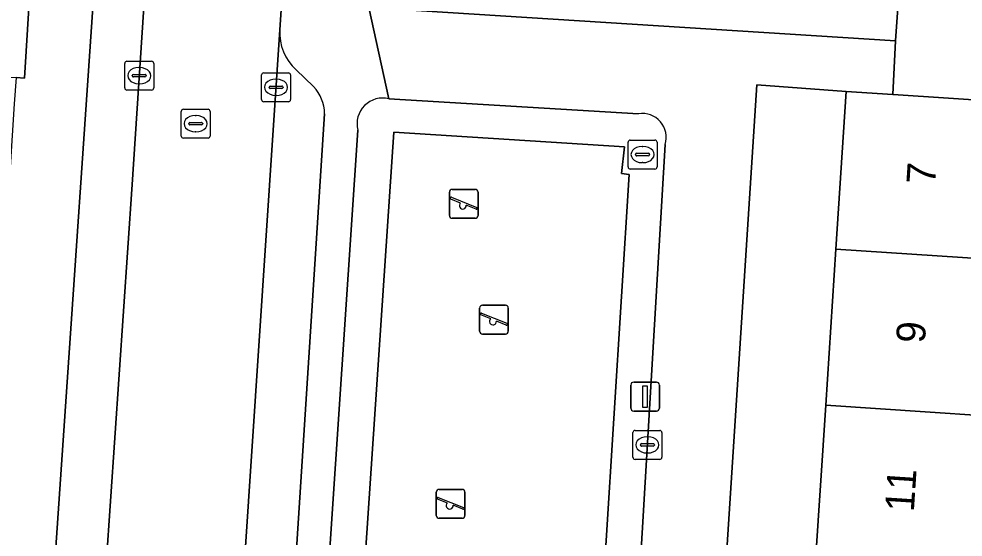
# Model space of a CAD drawing. Extents: x 160349 to 161355, y 381727 to 382854.
# Drawn here: x 160524.54 to 160557.19, y 382098.86 to 382116.79 of the extents above; entities that cross this region are included whole.
import ezdxf

# ---------------------------------------------------------------- set-up
doc = ezdxf.new("R2010")
doc.units = 0
for name, color, linetype in [('IMGEO_Erf', 7, 'Continuous'), ('IMGEO_Kolk', 7, 'Continuous'), ('IMGEO_Lichtmast', 7, 'Continuous'), ('IMGEO_Pand', 7, 'Continuous'), ('IMGEO_Pand_nummerreeks', 7, 'Continuous'), ('IMGEO_Parkeervlak_open', 7, 'Continuous'), ('IMGEO_Rijbaan_lokaal_open', 7, 'Continuous'), ('IMGEO_Rioolput', 7, 'Continuous'), ('IMGEO_Speelvoorziening', 7, 'Continuous'), ('IMGEO_Terreindeel_zand', 7, 'Continuous'), ('IMGEO_Voetpad_open', 7, 'Continuous')]:
    doc.layers.add(name, color=color, linetype=linetype)

msp = doc.modelspace()

# ---------------------------------------------------------------- linework, layer by layer
at = {"layer": 'IMGEO_Erf'}
msp.add_lwpolyline([(160554.283, 382136.365), (160554.009, 382131.874), (160551.075, 382132.055), (160551.131, 382132.964), (160549.023, 382133.094), (160549.242, 382136.673), (160546.917, 382136.849), (160546.586, 382131.4), (160543.46, 382131.59), (160536.662, 382132.003), (160536.289, 382127.236), (160535.964, 382122.847), (160535.525, 382117.245), (160536.641, 382117.175), (160554.852, 382116.032), (160555.553, 382126.006), (160556.133, 382134.259)], dxfattribs=at)
msp.add_lwpolyline([(160552.29, 382081.786), (160552.642, 382087.17), (160552.972, 382092.23), (160552.992, 382092.532), (160551.734, 382092.608), (160552.089, 382098.046), (160552.44, 382103.429), (160552.792, 382108.822), (160553.148, 382114.275), (160550.061, 382114.509), (160545.472, 382043.358), (160548.507, 382043.145), (160548.561, 382043.975), (160548.924, 382049.541), (160549.276, 382054.926), (160549.626, 382060.294), (160549.98, 382065.716), (160549.987, 382065.83), (160551.243, 382065.748), (160551.586, 382070.997), (160551.938, 382076.393)], close=True, dxfattribs=at)
at = {"layer": 'IMGEO_Kolk'}
for p, q in [((160528.281, 382115.323), (160529.133, 382115.323)), ((160528.206, 382114.397), (160528.206, 382115.249)), ((160528.694, 382115.103), (160528.719, 382115.103)), ((160529.207, 382115.249), (160529.207, 382114.397)), ((160528.465, 382114.817), (160528.465, 382114.829)), ((160528.903, 382114.78), (160528.505, 382114.78)), ((160528.508, 382114.866), (160528.906, 382114.866)), ((160528.949, 382114.829), (160528.949, 382114.817)), ((160532.935, 382113.994), (160532.935, 382114.846)), ((160533.01, 382114.92), (160533.862, 382114.92)), ((160533.423, 382114.7), (160533.448, 382114.7)), ((160533.936, 382114.846), (160533.936, 382113.994)), ((160529.133, 382114.323), (160528.281, 382114.323)), ((160528.717, 382114.543), (160528.692, 382114.543)), ((160533.194, 382114.414), (160533.194, 382114.426)), ((160533.632, 382114.377), (160533.234, 382114.377)), ((160533.237, 382114.463), (160533.635, 382114.463)), ((160533.678, 382114.426), (160533.678, 382114.414)), ((160533.446, 382114.14), (160533.421, 382114.14)), ((160533.862, 382113.92), (160533.01, 382113.92)), ((160545.773, 382101.626), (160545.773, 382102.478)), ((160545.848, 382102.552), (160546.7, 382102.552)), ((160546.261, 382102.332), (160546.286, 382102.332)), ((160546.774, 382102.478), (160546.774, 382101.626)), ((160546.032, 382102.046), (160546.032, 382102.058)), ((160546.47, 382102.009), (160546.072, 382102.009)), ((160546.075, 382102.095), (160546.473, 382102.095)), ((160546.516, 382102.058), (160546.516, 382102.046)), ((160546.284, 382101.772), (160546.259, 382101.772)), ((160546.7, 382101.552), (160545.848, 382101.552))]:
    msp.add_line(p, q, dxfattribs=at)
for points in [[(160528.281, 382115.323), (160529.133, 382115.323)], [(160528.206, 382114.397), (160528.206, 382115.249)], [(160529.207, 382115.249), (160529.207, 382114.397)], [(160532.935, 382113.994), (160532.935, 382114.846)], [(160533.01, 382114.92), (160533.862, 382114.92)], [(160533.936, 382114.846), (160533.936, 382113.994)], [(160529.133, 382114.323), (160528.281, 382114.323)], [(160533.862, 382113.92), (160533.01, 382113.92)], [(160545.773, 382101.626), (160545.773, 382102.478)], [(160545.848, 382102.552), (160546.7, 382102.552)], [(160546.774, 382102.478), (160546.774, 382101.626)], [(160546.7, 382101.552), (160545.848, 382101.552)]]:
    msp.add_lwpolyline(points, dxfattribs=at)
for centre, radius, start, end in [((160528.283, 382115.247), 0.0765, 91.552, 178.448), ((160528.283, 382115.247), 0.0765, 91.552, 178.448), ((160529.131, 382115.247), 0.0765, 1.552, 88.448), ((160529.131, 382115.247), 0.0765, 1.552, 88.448), ((160528.505, 382114.826), 0.0403, 85.8775, 175.7526), ((160528.502, 382114.816), 0.0366, 178.938, 274.7102), ((160528.906, 382114.823), 0.043, 264.8664, 352.4533), ((160528.91, 382114.828), 0.0386, 1.7309, 96.639), ((160533.012, 382114.844), 0.0765, 91.552, 178.448), ((160533.012, 382114.844), 0.0765, 91.552, 178.448), ((160533.86, 382114.844), 0.0765, 1.552, 88.448), ((160533.86, 382114.844), 0.0765, 1.552, 88.448), ((160528.283, 382114.399), 0.0765, 181.552, 268.448), ((160528.283, 382114.399), 0.0765, 181.552, 268.448), ((160529.131, 382114.399), 0.0765, 271.552, 358.448), ((160529.131, 382114.399), 0.0765, 271.552, 358.448), ((160533.234, 382114.423), 0.0403, 85.8775, 175.7526), ((160533.231, 382114.413), 0.0366, 178.938, 274.7102), ((160533.635, 382114.42), 0.043, 264.8664, 352.4533), ((160533.639, 382114.425), 0.0386, 1.7309, 96.639), ((160533.012, 382113.996), 0.0765, 181.552, 268.448), ((160533.012, 382113.996), 0.0765, 181.552, 268.448), ((160533.86, 382113.996), 0.0765, 271.552, 358.448), ((160533.86, 382113.996), 0.0765, 271.552, 358.448), ((160545.85, 382102.476), 0.0765, 91.552, 178.448), ((160545.85, 382102.476), 0.0765, 91.552, 178.448), ((160546.698, 382102.476), 0.0765, 1.552, 88.448), ((160546.698, 382102.476), 0.0765, 1.552, 88.448), ((160546.072, 382102.055), 0.0403, 85.8775, 175.7526), ((160546.069, 382102.045), 0.0366, 178.938, 274.7102), ((160546.473, 382102.052), 0.043, 264.8664, 352.4533), ((160546.477, 382102.057), 0.0386, 1.7309, 96.639), ((160545.85, 382101.628), 0.0765, 181.552, 268.448), ((160545.85, 382101.628), 0.0765, 181.552, 268.448), ((160546.698, 382101.628), 0.0765, 271.552, 358.448), ((160546.698, 382101.628), 0.0765, 271.552, 358.448)]:
    msp.add_arc(centre, radius, start, end, dxfattribs=at)
for centre, major_axis, ratio, start_param, end_param in [((160528.693, 382114.823), (-0.387, 0.002), 0.722429, 4.712389, 7.853982), ((160528.718, 382114.823), (-0.39, 0.002), 0.717154, 1.570796, 4.712389), ((160533.422, 382114.42), (-0.387, 0.002), 0.722429, 4.712389, 7.853982), ((160533.447, 382114.42), (-0.39, 0.002), 0.717154, 1.570796, 4.712389), ((160546.26, 382102.052), (-0.387, 0.002), 0.722429, 4.712389, 7.853982), ((160546.285, 382102.052), (-0.39, 0.002), 0.717154, 1.570796, 4.712389)]:
    msp.add_ellipse(centre, major_axis=major_axis, ratio=ratio, start_param=start_param, end_param=end_param, dxfattribs=at)
at = {"layer": 'IMGEO_Lichtmast'}
for p, q in [((160545.8, 382104.223), (160546.59, 382104.223)), ((160546.59, 382104.223), (160545.8, 382104.223)), ((160545.7, 382103.323), (160545.7, 382104.123)), ((160545.7, 382104.123), (160545.7, 382103.323)), ((160546.69, 382104.123), (160546.69, 382103.323)), ((160546.69, 382103.323), (160546.69, 382104.123)), ((160546.59, 382103.223), (160545.8, 382103.223)), ((160545.8, 382103.223), (160546.59, 382103.223))]:
    msp.add_line(p, q, dxfattribs=at)
msp.add_lwpolyline([(160546.12, 382104.098), (160546.27, 382104.098), (160546.27, 382103.348), (160546.12, 382103.348), (160546.12, 382104.098)], dxfattribs=at)
for centre, start, end in [((160545.8, 382104.123), 90, 180), ((160545.8, 382104.123), 90, 180), ((160546.59, 382104.123), 0, 90), ((160546.59, 382104.123), 360, 90), ((160545.8, 382103.323), 180, 270), ((160545.8, 382103.323), 180, 270), ((160546.59, 382103.323), 270, 0), ((160546.59, 382103.323), 270, 0)]:
    msp.add_arc(centre, 0.1, start, end, dxfattribs=at)
at = {"layer": 'IMGEO_Pand'}
for points in [[(160525.112, 382120.73), (160524.717, 382120.755), (160520.122, 382121.044), (160517.634, 382121.199), (160517.73, 382122.642), (160513.499, 382125.419), (160511.676, 382122.468), (160516.039, 382119.822), (160515.739, 382115.319), (160519.745, 382115.053), (160524.448, 382114.756), (160524.735, 382114.738)], [(160565.063, 382113.497), (160562.083, 382113.691), (160554.776, 382114.169), (160554.755, 382114.17), (160553.148, 382114.275), (160552.792, 382108.822), (160561.726, 382108.23), (160561.911, 382111.057), (160564.891, 382110.863)], [(160561.374, 382102.83), (160561.726, 382108.23), (160552.792, 382108.822), (160552.44, 382103.429)], [(160561.374, 382102.83), (160552.44, 382103.429), (160552.089, 382098.046), (160561.022, 382097.439), (160563.676, 382097.259), (160564.028, 382102.652)]]:
    msp.add_lwpolyline(points, close=True, dxfattribs=at)
at = {"layer": 'IMGEO_Parkeervlak_open'}
for points in [[(160526.212, 382078.198), (160528.46, 382111.058), (160529.2, 382122.284), (160529.238, 382122.868)], [(160527.294, 382120.049), (160524.642, 382081.346)], [(160533.568, 382116.409), (160532.124, 382094.725)], [(160534.734, 382114.448), (160534.137, 382115.02)], [(160534.107, 382097.903), (160535.114, 382113.508)]]:
    msp.add_lwpolyline(points, dxfattribs=at)
for centre, radius, start, end in [((160535.284, 382116.301), 1.72, 176.3988, 228.1539), ((160533.668, 382113.47), 1.447, 1.4992, 42.5234)]:
    msp.add_arc(centre, radius, start, end, dxfattribs=at)
at = {"layer": 'IMGEO_Rijbaan_lokaal_open'}
msp.add_lwpolyline([(160532.124, 382094.725), (160533.568, 382116.409), (160533.754, 382119.181), (160533.945, 382121.958), (160529.2, 382122.284), (160528.46, 382111.058), (160526.212, 382078.198), (160526.177, 382077.688), (160530.952, 382077.354), (160531, 382078.07), (160532.095, 382094.296)], close=True, dxfattribs=at)
at = {"layer": 'IMGEO_Rioolput'}
for p, q in [((160530.157, 382112.736), (160530.157, 382113.588)), ((160530.232, 382113.662), (160531.084, 382113.662)), ((160530.645, 382113.442), (160530.67, 382113.442)), ((160531.158, 382113.588), (160531.158, 382112.736)), ((160530.416, 382113.156), (160530.416, 382113.168)), ((160530.854, 382113.119), (160530.456, 382113.119)), ((160530.459, 382113.205), (160530.857, 382113.205)), ((160530.9, 382113.168), (160530.9, 382113.156)), ((160530.668, 382112.882), (160530.643, 382112.882)), ((160531.084, 382112.662), (160530.232, 382112.662)), ((160545.607, 382111.668), (160545.607, 382112.52)), ((160545.682, 382112.594), (160546.534, 382112.594)), ((160546.095, 382112.374), (160546.12, 382112.374)), ((160546.608, 382112.52), (160546.608, 382111.668)), ((160545.866, 382112.088), (160545.866, 382112.1)), ((160546.304, 382112.051), (160545.906, 382112.051)), ((160545.909, 382112.137), (160546.307, 382112.137)), ((160546.35, 382112.1), (160546.35, 382112.088)), ((160546.118, 382111.814), (160546.093, 382111.814)), ((160546.534, 382111.594), (160545.682, 382111.594))]:
    msp.add_line(p, q, dxfattribs=at)
for points in [[(160530.157, 382112.736), (160530.157, 382113.588)], [(160530.232, 382113.662), (160531.084, 382113.662)], [(160531.158, 382113.588), (160531.158, 382112.736)], [(160531.084, 382112.662), (160530.232, 382112.662)], [(160545.607, 382111.668), (160545.607, 382112.52)], [(160545.682, 382112.594), (160546.534, 382112.594)], [(160546.608, 382112.52), (160546.608, 382111.668)], [(160546.534, 382111.594), (160545.682, 382111.594)]]:
    msp.add_lwpolyline(points, dxfattribs=at)
for centre, radius, start, end in [((160530.234, 382113.586), 0.0765, 91.552, 178.448), ((160530.234, 382113.586), 0.0765, 91.552, 178.448), ((160531.082, 382113.586), 0.0765, 1.552, 88.448), ((160531.082, 382113.586), 0.0765, 1.552, 88.448), ((160530.456, 382113.165), 0.0403, 85.8775, 175.7526), ((160530.453, 382113.155), 0.0366, 178.938, 274.7102), ((160530.857, 382113.162), 0.043, 264.8664, 352.4533), ((160530.861, 382113.167), 0.0386, 1.7309, 96.639), ((160530.234, 382112.738), 0.0765, 181.552, 268.448), ((160530.234, 382112.738), 0.0765, 181.552, 268.448), ((160531.082, 382112.738), 0.0765, 271.552, 358.448), ((160531.082, 382112.738), 0.0765, 271.552, 358.448), ((160545.684, 382112.518), 0.0765, 91.552, 178.448), ((160545.684, 382112.518), 0.0765, 91.552, 178.448), ((160546.532, 382112.518), 0.0765, 1.552, 88.448), ((160546.532, 382112.518), 0.0765, 1.552, 88.448), ((160545.906, 382112.097), 0.0403, 85.8775, 175.7526), ((160545.903, 382112.087), 0.0366, 178.938, 274.7102), ((160546.307, 382112.094), 0.043, 264.8664, 352.4533), ((160546.311, 382112.099), 0.0386, 1.7309, 96.639), ((160545.684, 382111.67), 0.0765, 181.552, 268.448), ((160545.684, 382111.67), 0.0765, 181.552, 268.448), ((160546.532, 382111.67), 0.0765, 271.552, 358.448), ((160546.532, 382111.67), 0.0765, 271.552, 358.448)]:
    msp.add_arc(centre, radius, start, end, dxfattribs=at)
for centre, major_axis, ratio, start_param, end_param in [((160530.644, 382113.162), (-0.387, 0.002), 0.722429, 4.712389, 7.853982), ((160530.669, 382113.162), (-0.39, 0.002), 0.717154, 1.570796, 4.712389), ((160546.094, 382112.094), (-0.387, 0.002), 0.722429, 4.712389, 7.853982), ((160546.119, 382112.094), (-0.39, 0.002), 0.717154, 1.570796, 4.712389)]:
    msp.add_ellipse(centre, major_axis=major_axis, ratio=ratio, start_param=start_param, end_param=end_param, dxfattribs=at)
at = {"layer": 'IMGEO_Speelvoorziening'}
for p, q in [((160539.429, 382109.99), (160539.429, 382110.79)), ((160539.429, 382110.79), (160539.429, 382109.99)), ((160539.529, 382110.89), (160540.319, 382110.89)), ((160540.319, 382110.89), (160539.529, 382110.89)), ((160540.419, 382110.79), (160540.419, 382109.99)), ((160540.419, 382109.99), (160540.419, 382110.79)), ((160539.812, 382110.418), (160539.473, 382110.555)), ((160539.498, 382110.615), (160540.374, 382110.262)), ((160540.35, 382110.202), (160540.01, 382110.339)), ((160540.319, 382109.89), (160539.529, 382109.89)), ((160539.529, 382109.89), (160540.319, 382109.89)), ((160540.573, 382106.885), (160541.363, 382106.885)), ((160541.363, 382106.885), (160540.573, 382106.885)), ((160540.473, 382105.985), (160540.473, 382106.785)), ((160540.473, 382106.785), (160540.473, 382105.985)), ((160540.856, 382106.413), (160540.517, 382106.55)), ((160540.542, 382106.61), (160541.418, 382106.257)), ((160541.463, 382106.785), (160541.463, 382105.985)), ((160541.463, 382105.985), (160541.463, 382106.785)), ((160541.394, 382106.197), (160541.054, 382106.334)), ((160541.363, 382105.885), (160540.573, 382105.885)), ((160540.573, 382105.885), (160541.363, 382105.885)), ((160538.976, 382099.613), (160538.976, 382100.413)), ((160538.976, 382100.413), (160538.976, 382099.613)), ((160539.076, 382100.513), (160539.866, 382100.513)), ((160539.866, 382100.513), (160539.076, 382100.513)), ((160539.966, 382100.413), (160539.966, 382099.613)), ((160539.966, 382099.613), (160539.966, 382100.413)), ((160539.359, 382100.041), (160539.02, 382100.178)), ((160539.045, 382100.238), (160539.921, 382099.885)), ((160539.897, 382099.825), (160539.557, 382099.962)), ((160539.866, 382099.513), (160539.076, 382099.513)), ((160539.076, 382099.513), (160539.866, 382099.513))]:
    msp.add_line(p, q, dxfattribs=at)
for centre, radius, start, end in [((160539.529, 382110.79), 0.1, 90, 180), ((160539.529, 382110.79), 0.1, 90, 180), ((160540.319, 382110.79), 0.1, 0, 90), ((160540.319, 382110.79), 0.1, 360, 90), ((160539.486, 382110.585), 0.0327, 68.078, 248.078), ((160539.891, 382110.328), 0.12, 130.9928, 5.1632), ((160540.362, 382110.232), 0.0327, 248.078, 68.078), ((160539.529, 382109.99), 0.1, 180, 270), ((160539.529, 382109.99), 0.1, 180, 270), ((160540.319, 382109.99), 0.1, 270, 0), ((160540.319, 382109.99), 0.1, 270, 0), ((160540.573, 382106.785), 0.1, 90, 180), ((160540.573, 382106.785), 0.1, 90, 180), ((160541.363, 382106.785), 0.1, 0, 90), ((160541.363, 382106.785), 0.1, 360, 90), ((160540.53, 382106.58), 0.0327, 68.078, 248.078), ((160540.935, 382106.323), 0.12, 130.9928, 5.1632), ((160541.406, 382106.227), 0.0327, 248.078, 68.078), ((160540.573, 382105.985), 0.1, 180, 270), ((160540.573, 382105.985), 0.1, 180, 270), ((160541.363, 382105.985), 0.1, 270, 0), ((160541.363, 382105.985), 0.1, 270, 0), ((160539.076, 382100.413), 0.1, 90, 180), ((160539.076, 382100.413), 0.1, 90, 180), ((160539.866, 382100.413), 0.1, 0, 90), ((160539.866, 382100.413), 0.1, 360, 90), ((160539.033, 382100.208), 0.0327, 68.078, 248.078), ((160539.438, 382099.951), 0.12, 130.9928, 5.1632), ((160539.909, 382099.855), 0.0327, 248.078, 68.078), ((160539.076, 382099.613), 0.1, 180, 270), ((160539.076, 382099.613), 0.1, 180, 270), ((160539.866, 382099.613), 0.1, 270, 0), ((160539.866, 382099.613), 0.1, 270, 0)]:
    msp.add_arc(centre, radius, start, end, dxfattribs=at)
at = {"layer": 'IMGEO_Terreindeel_zand'}
msp.add_lwpolyline([(160544.32, 382090.302), (160545.641, 382111.4), (160545.374, 382111.436), (160545.482, 382112.364), (160537.505, 382112.874), (160536.026, 382090.785)], close=True, dxfattribs=at)
at = {"layer": 'IMGEO_Voetpad_open'}
for points in [[(160526.439, 382144.267), (160524.717, 382120.755), (160525.112, 382120.73), (160524.735, 382114.738), (160524.448, 382114.756), (160524.387, 382113.848), (160524.04, 382108.368), (160523.728, 382103.398), (160523.403, 382098.257), (160523.069, 382092.946), (160522.968, 382092.016), (160522.64, 382086.81), (160522.312, 382081.61), (160521.987, 382076.49), (160521.657, 382071.207), (160521.557, 382069.746), (160520.833, 382059.141)], [(160556.133, 382134.259), (160556.158, 382134.351), (160556.542, 382138.8), (160537.357, 382140.034), (160535.032, 382137.762), (160534.153, 382124.984), (160533.945, 382121.958), (160533.754, 382119.181), (160533.568, 382116.409)], [(160556.542, 382138.8), (160556.158, 382134.351), (160556.133, 382134.259), (160555.553, 382126.006), (160554.852, 382116.032), (160554.755, 382114.17), (160554.776, 382114.169), (160562.083, 382113.691), (160565.063, 382113.497), (160571.135, 382113.211), (160571.156, 382112.973), (160576.544, 382112.619), (160576.605, 382113.552), (160576.671, 382114.572)], [(160537.337, 382114.025), (160536.641, 382117.175), (160535.525, 382117.245), (160535.964, 382122.847), (160536.289, 382127.236), (160536.662, 382132.003), (160536.994, 382137.452), (160543.823, 382137.037), (160546.917, 382136.849), (160549.242, 382136.673), (160551.303, 382136.547), (160554.283, 382136.365)], [(160524.642, 382081.346), (160527.294, 382120.049)], [(160550.061, 382114.509), (160553.148, 382114.275), (160554.755, 382114.17), (160554.852, 382116.032), (160536.641, 382117.175), (160537.337, 382114.025), (160545.969, 382113.507)], [(160534.137, 382115.02), (160534.734, 382114.448)], [(160541.81, 382045.609), (160532.964, 382046.126), (160528.807, 382045.931), (160528.662, 382043.535), (160530.648, 382043.401), (160545.411, 382042.407), (160545.472, 382043.358), (160550.061, 382114.509)], [(160545.969, 382113.507), (160537.337, 382114.025)], [(160535.114, 382113.508), (160534.107, 382097.903)], [(160534.374, 382084.644), (160534.721, 382089.841), (160536.261, 382112.942)], [(160536.261, 382112.942), (160534.721, 382089.841), (160535.629, 382089.776), (160545.503, 382089.073), (160546.889, 382112.44)], [(160546.889, 382112.44), (160545.503, 382089.073), (160545.217, 382084.257)]]:
    msp.add_lwpolyline(points, dxfattribs=at)
msp.add_lwpolyline([(160545.482, 382112.364), (160545.374, 382111.436), (160545.641, 382111.4), (160544.32, 382090.302), (160536.026, 382090.785), (160537.505, 382112.874)], close=True, dxfattribs=at)
for centre, radius, start, end in [((160535.284, 382116.301), 1.72, 176.3988, 228.1539), ((160533.668, 382113.47), 1.447, 1.4992, 42.5234), ((160537.127, 382113.158), 0.892, 76.3671, 194.0044), ((160537.127, 382113.158), 0.892, 76.3671, 194.0044), ((160546.097, 382112.687), 0.83, 342.7008, 98.837), ((160546.097, 382112.687), 0.83, 342.7008, 98.837)]:
    msp.add_arc(centre, radius, start, end, dxfattribs=at)

# ---------------------------------------------------------------- texts
at = {"layer": 'IMGEO_Pand_nummerreeks'}
for s, rotation, p in [('7', 86.2645, (160556.224, 382111.041)), ('9', 86.2668, (160555.865, 382105.55)), ('11', 86.2645, (160555.485, 382099.716))]:
    msp.add_text(s, height=1, rotation=rotation, dxfattribs=at).set_placement(p)

doc.saveas('drawing.dxf')
